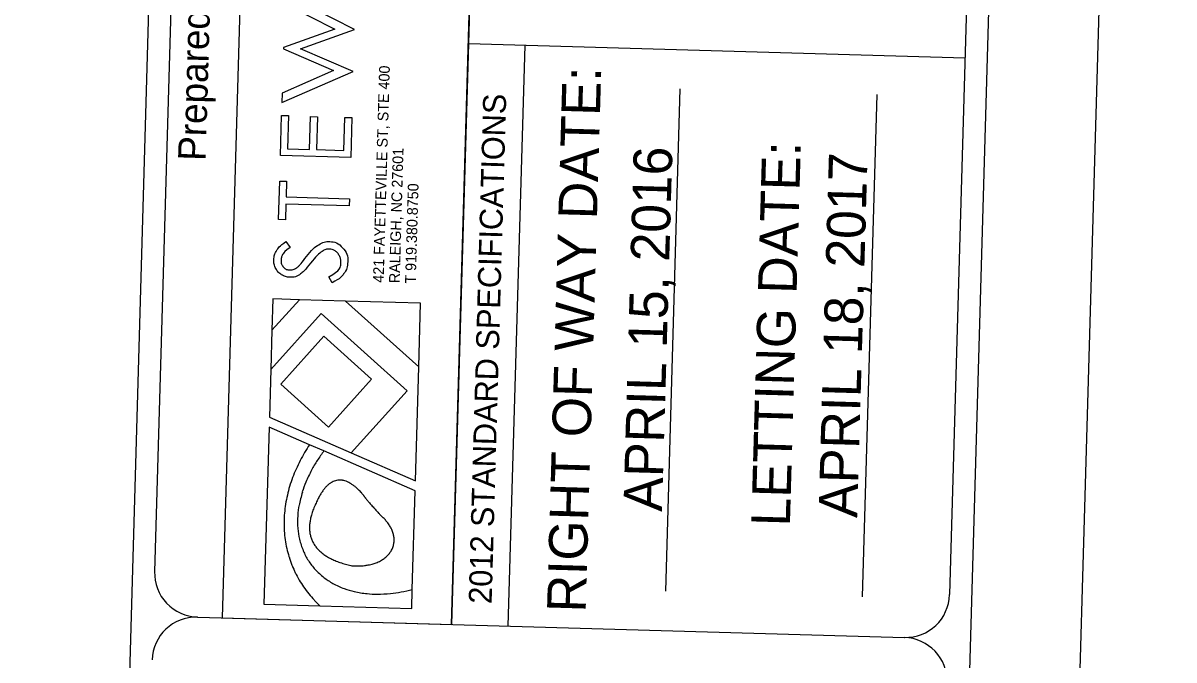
# Model space of a CAD drawing. Extents: x 2097846 to 2099709, y 989477 to 992073.
# Drawn here: x 2099177.8 to 2099568.5, y 990925.3 to 991141.6 of the extents above; entities that cross this region are included whole.
import ezdxf

# ---------------------------------------------------------------- set-up
doc = ezdxf.new("R2010")
doc.units = 0
for name, color, linetype in [('Sheet Data Field CELL', 7, 'Continuous'), ('Sheet Title CELL', 7, 'Continuous'), ('Stewart Logo', 7, 'Continuous'), ('Stewart Plot Border Xerox6279 and LJ5000', 7, 'Continuous')]:
    doc.layers.add(name, color=color, linetype=linetype)

msp = doc.modelspace()

# ---------------------------------------------------------------- linework, layer by layer
at = {"layer": 'Sheet Title CELL'}
for p, q in [((2099183.04, 989845.97), (2099244.37, 991975.08)), ((2099336.46, 991394.69), (2099328.96, 991134.63)), ((2099222.5, 990955.29), (2099234.81, 991382.61)), ((2099328.96, 991134.63), (2099323.27, 990937.38)), ((2099328.96, 991134.63), (2099497.63, 991129.77)), ((2099348.09, 991134.07), (2099342.39, 990936.83)), ((2099400.72, 991119.2), (2099395.81, 990948.65)), ((2099467.59, 991117.28), (2099462.68, 990946.72)), ((2099346.44, 991077.25), (2099346.44, 991077.25)), ((2099398.28, 991033.67), (2099398.28, 991033.67)), ((2099237.06, 990939.87), (2099476.96, 990932.96))]:
    msp.add_line(p, q, dxfattribs=at)
for points in [[(2099465.57, 989755.3), (2099529.49, 991974.37)], [(2099492.39, 990947.52), (2099504.71, 991374.84)]]:
    msp.add_lwpolyline(points, dxfattribs=at)
msp.add_lwpolyline([(2099323.27, 990937.38), (2099336.45, 991394.69), (2099258.59, 991396.94), (2099245.41, 990939.63)], close=True, dxfattribs=at)
for centre, start, end in [((2099237.42, 990954.87), 178.35, 268.35), ((2099477.32, 990947.96), 268.35, 358.35), ((2099236.56, 990924.88), 88.35, 178.35), ((2099476.46, 990917.97), 358.35, 88.35)]:
    msp.add_arc(centre, 15, start, end, dxfattribs=at)
at = {"layer": 'Stewart Logo'}
for p, q in [((2099290.24, 991139.44), (2099266.72, 991151.39)), ((2099266.63, 991148.14), (2099283.58, 991139.53)), ((2099283.58, 991139.53), (2099266.2, 991133.27)), ((2099271.99, 991132.87), (2099290.24, 991139.44)), ((2099266.2, 991133.27), (2099266.19, 991132.81)), ((2099266.19, 991132.81), (2099283.17, 991125.44)), ((2099289.83, 991125.1), (2099271.99, 991132.87)), ((2099265.66, 991114.57), (2099289.83, 991125.1)), ((2099283.17, 991125.44), (2099265.75, 991117.82)), ((2099265.75, 991117.82), (2099265.66, 991114.57)), ((2099262.54, 991047.91), (2099262.24, 991037.32)), ((2099271.56, 991047.65), (2099262.54, 991047.91)), ((2099262.24, 991037.32), (2099271.56, 991047.65)), ((2099271.56, 991047.65), (2099262.24, 991037.32)), ((2099287.27, 991047.19), (2099271.56, 991047.65)), ((2099312.7, 991046.46), (2099287.27, 991047.19)), ((2099287.27, 991047.19), (2099312.07, 991024.81)), ((2099312.07, 991024.81), (2099287.27, 991047.19)), ((2099312.07, 991024.81), (2099312.7, 991046.46)), ((2099261.85, 991023.98), (2099279.02, 991042.99)), ((2099279.02, 991042.99), (2099261.85, 991023.98)), ((2099279.02, 991042.99), (2099308.16, 991016.68)), ((2099308.16, 991016.68), (2099279.02, 991042.99)), ((2099262.24, 991037.32), (2099261.85, 991023.98)), ((2099296.11, 991020.63), (2099279.93, 991035.23)), ((2099310.96, 990986.15), (2099312.07, 991024.81)), ((2099261.85, 991023.98), (2099261.39, 991007.76)), ((2099308.16, 991016.68), (2099289.17, 990995.65)), ((2099289.17, 990995.65), (2099308.16, 991016.68)), ((2099261.39, 991007.76), (2099289.17, 990995.65)), ((2099261.29, 991004.41), (2099259.56, 990944.25)), ((2099275.05, 990998.41), (2099261.29, 991004.41)), ((2099279.92, 990996.28), (2099275.05, 990998.41)), ((2099271.84, 990993.01), (2099271.85, 990993.02)), ((2099310.86, 990982.79), (2099279.92, 990996.28)), ((2099289.17, 990995.65), (2099310.96, 990986.15)), ((2099309.9, 990949.27), (2099310.86, 990982.79)), ((2099266.88, 990978.19), (2099266.88, 990978.22)), ((2099271.52, 990977.82), (2099271.47, 990977.93)), ((2099268.03, 990960.4), (2099268.07, 990960.28)), ((2099269.05, 990957.47), (2099269.13, 990957.39)), ((2099309.71, 990942.8), (2099309.9, 990949.27)), ((2099259.56, 990944.25), (2099278.5, 990943.7)), ((2099278.5, 990943.7), (2099309.71, 990942.8))]:
    msp.add_line(p, q, dxfattribs=at)
for points in [[(2099265.14, 991096.56), (2099265.54, 991110.23), (2099267.87, 991110.16), (2099267.55, 991098.87), (2099275.02, 991098.65), (2099275.34, 991109.85), (2099277.68, 991109.78), (2099277.36, 991098.59), (2099286.72, 991098.32), (2099287.04, 991109.51), (2099289.38, 991109.45), (2099288.99, 991095.87), (2099265.14, 991096.56)], [(2099266.85, 991074.81), (2099264.52, 991074.88), (2099264.89, 991087.93), (2099267.23, 991087.86), (2099267.08, 991082.55), (2099288.59, 991081.93), (2099288.52, 991079.5), (2099267.01, 991080.12), (2099266.85, 991074.81)], [(2099267.02, 991067.38), (2099268.44, 991065.39)], [(2099282.72, 991053.38), (2099281.56, 991055.44)], [(2099281.44, 991004.38), (2099265.26, 991018.99), (2099279.93, 991035.23), (2099296.11, 991020.63), (2099281.44, 991004.38)], [(2099279.93, 991035.23), (2099265.26, 991018.99), (2099281.44, 991004.38), (2099296.11, 991020.63)], [(2099272.56, 990982.35), (2099272.62, 990982.23)], [(2099293.23, 990981.42), (2099293.33, 990981.23)], [(2099293.44, 990981.06), (2099293.6, 990980.84)], [(2099293.81, 990980.55), (2099294.08, 990980.22)], [(2099299.21, 990974.4), (2099299.48, 990974.12)], [(2099270.26, 990954.82), (2099270.15, 990955.03)], [(2099276.58, 990945.68), (2099276.69, 990945.52)]]:
    msp.add_lwpolyline(points, dxfattribs=at)
for centre, radius, start, end in [((2099319.69, 990968.23), 53.89, 145.9418, 149.2779), ((2099319.69, 990968.23), 53.89, 145.9418, 149.2779), ((2099321.71, 990967.2), 56.15, 152.6242, 155.9604), ((2099321.71, 990967.2), 56.15, 152.6242, 155.9604), ((2099319.69, 990968.23), 53.89, 149.2779, 152.6242), ((2099319.69, 990968.23), 53.89, 149.2779, 152.6242), ((2099313.79, 990969.69), 43.05, 147.1279, 152.1473), ((2099313.79, 990969.69), 43.05, 147.1279, 152.1473), ((2099317.43, 990967.34), 47.37, 142.3433, 147.1279), ((2099317.43, 990967.34), 47.37, 142.3433, 147.1279), ((2099314.06, 990970.62), 47.77, 155.9604, 159.5775), ((2099314.06, 990970.62), 47.77, 155.9604, 159.5775), ((2099323.93, 990964.33), 54.51, 152.1473, 156.9319), ((2099323.93, 990964.33), 54.51, 152.1473, 156.9319), ((2099317.02, 990969.51), 50.93, 159.5775, 163.213), ((2099317.02, 990969.51), 50.93, 159.5775, 163.213), ((2099304.36, 990972.67), 33.24, 156.9319, 163.0599), ((2099304.36, 990972.67), 33.24, 156.9319, 163.0599), ((2099286.42, 990978.96), 7.73, 122.2457, 129.1263), ((2099286.42, 990978.96), 7.73, 122.2457, 129.1263), ((2099285.58, 990980.28), 6.16, 114.5378, 122.2457), ((2099285.58, 990980.28), 6.16, 114.5378, 122.2457), ((2099285.4, 990980.69), 5.72, 106.2089, 114.5378), ((2099285.4, 990980.69), 5.72, 106.2089, 114.5378), ((2099285.27, 990981.13), 5.26, 97.5206, 106.2089), ((2099285.27, 990981.13), 5.26, 97.5206, 106.2089), ((2099285.27, 990981.12), 5.27, 88.8565, 97.5206), ((2099285.27, 990981.12), 5.27, 88.8565, 97.5206), ((2099285.26, 990980.59), 5.8, 80.5939, 88.8565), ((2099285.26, 990980.59), 5.8, 80.5939, 88.8565), ((2099285.18, 990980.12), 6.27, 72.98, 80.5939), ((2099285.18, 990980.12), 6.27, 72.98, 80.5939), ((2099284.7, 990978.55), 7.92, 66.2041, 72.98), ((2099284.7, 990978.55), 7.92, 66.2041, 72.98), ((2099284.29, 990977.63), 8.93, 60.2402, 66.2041), ((2099284.29, 990977.63), 8.93, 60.2402, 66.2041), ((2099282.75, 990974.93), 12.03, 55.1034, 60.2402), ((2099282.75, 990974.93), 12.03, 55.1034, 60.2402), ((2099312.48, 990971), 46.16, 167.0996, 171.0318), ((2099312.48, 990971), 46.16, 167.0996, 171.0318), ((2099310.92, 990971.35), 44.56, 163.213, 167.0996), ((2099310.92, 990971.35), 44.56, 163.213, 167.0996), ((2099313.79, 990969.69), 43.05, 163.0599, 169.1132), ((2099313.79, 990969.69), 43.05, 163.0599, 169.1132), ((2099299.04, 990969.46), 23.62, 148.8587, 152.2518), ((2099299.04, 990969.46), 23.62, 148.8587, 152.2518), ((2099294.38, 990972.28), 18.17, 144.971, 148.8587), ((2099294.38, 990972.28), 18.17, 144.971, 148.8587), ((2099290.38, 990975.08), 13.29, 140.4253, 144.971), ((2099290.38, 990975.08), 13.29, 140.4253, 144.971), ((2099289.16, 990976.09), 11.7, 135.194, 140.4253), ((2099289.16, 990976.09), 11.7, 135.194, 140.4253), ((2099287.03, 990978.21), 8.7, 129.1263, 135.194), ((2099287.03, 990978.21), 8.7, 129.1263, 135.194), ((2099281.81, 990973.59), 13.67, 50.6411, 55.1034), ((2099281.81, 990973.59), 13.67, 50.6411, 55.1034), ((2099278.64, 990969.72), 18.67, 46.824, 50.6411), ((2099278.64, 990969.72), 18.67, 46.824, 50.6411), ((2099274.82, 990965.65), 24.25, 43.4909, 46.824), ((2099274.82, 990965.65), 24.25, 43.4909, 46.824), ((2099279, 990969.62), 18.49, 39.6738, 43.4909), ((2099279, 990969.62), 18.49, 39.6738, 43.4909), ((2099296.28, 990982.77), 3.33, 203.8541, 206.4104), ((2099293.91, 990981.59), 0.68, 206.4103, 212.0676), ((2099308.49, 990971.65), 42.12, 171.0318, 175.1641), ((2099308.49, 990971.65), 42.12, 171.0318, 175.1641), ((2099298.8, 990972.68), 27.83, 169.1132, 176.6486), ((2099298.8, 990972.68), 27.83, 169.1132, 176.6486), ((2099303.1, 990966.26), 28.67, 156.1495, 159.8788), ((2099303.1, 990966.26), 28.67, 156.1495, 159.8788), ((2099297.87, 990968.57), 22.95, 151.9816, 156.1495), ((2099297.87, 990968.57), 22.95, 151.9816, 156.1495), ((2099294.06, 990972.08), 17.99, 152.2518, 156.1394), ((2099294.06, 990972.08), 17.99, 152.2518, 156.1394), ((2099297.13, 990983.61), 4.48, 212.0675, 214.6237), ((2099297.13, 990983.61), 4.48, 212.0675, 214.6237), ((2099300.49, 990985.93), 8.57, 214.6237, 216.4714), ((2099308.09, 990991.55), 18.02, 216.4714, 217.5989), ((2099308.09, 990991.55), 18.02, 216.4714, 217.5989), ((2099314.39, 990996.4), 25.97, 217.5989, 218.5383), ((2099327.78, 991007.06), 43.09, 218.5383, 219.2146), ((2099327.78, 991007.06), 43.09, 218.5383, 219.2146), ((2099337.08, 991014.65), 55.09, 219.2146, 219.8128), ((2099337.08, 991014.65), 55.09, 219.2146, 219.8128), ((2099351.65, 991026.8), 74.06, 219.8128, 220.3011), ((2099351.65, 991026.8), 74.06, 219.8128, 220.3011), ((2099363.88, 991037.17), 90.1, 220.3011, 220.7439), ((2099363.88, 991037.17), 90.1, 220.3011, 220.7439), ((2099370.57, 991042.93), 98.93, 220.7439, 221.1471), ((2099370.57, 991042.93), 98.93, 220.7439, 221.1471), ((2099385.16, 991055.68), 118.3, 221.1471, 221.5158), ((2099385.16, 991055.68), 118.3, 221.1471, 221.5158), ((2099308.49, 990971.65), 42.12, 175.1641, 179.3637), ((2099308.49, 990971.65), 42.12, 175.1641, 179.3637), ((2099303.56, 990972.4), 32.6, 176.6486, 184.3198), ((2099303.56, 990972.4), 32.6, 176.6486, 184.3198), ((2099292.93, 990969.59), 17.96, 164.0466, 168.7766), ((2099292.93, 990969.59), 17.96, 164.0466, 168.7766), ((2099297.89, 990968.17), 23.13, 159.8788, 164.0466), ((2099297.89, 990968.17), 23.13, 159.8788, 164.0466), ((2099376.9, 991048.37), 107.27, 221.5158, 221.8864), ((2099376.9, 991048.37), 107.27, 221.5158, 221.8864), ((2099392.11, 991062.01), 127.7, 221.8863, 222.2259), ((2099392.11, 991062.01), 127.7, 221.8863, 222.2259), ((2099369.73, 991041.7), 97.48, 222.2259, 222.5983), ((2099369.73, 991041.7), 97.48, 222.2259, 222.5983), ((2099382.96, 991053.87), 115.46, 222.5983, 222.9405), ((2099382.96, 991053.87), 115.46, 222.5983, 222.9405), ((2099354.18, 991027.08), 76.14, 222.9405, 223.345), ((2099354.18, 991027.08), 76.14, 222.9405, 223.345), ((2099363.5, 991035.88), 88.95, 223.345, 223.7193), ((2099363.5, 991035.88), 88.95, 223.345, 223.7193), ((2099333.62, 991007.31), 47.61, 223.7193, 224.1914), ((2099353.79, 991026.91), 75.73, 224.1914, 224.5657), ((2099353.79, 991026.91), 75.73, 224.1914, 224.5657), ((2099290.9, 990963.84), 13.35, 42.4064, 48.0117), ((2099290.9, 990963.84), 13.35, 42.4064, 48.0117), ((2099306.08, 990971.68), 39.71, 179.3637, 183.6885), ((2099306.08, 990971.68), 39.71, 179.3637, 183.6885), ((2099294.58, 990971.72), 23.59, 184.3198, 193.3394), ((2099294.58, 990971.72), 23.59, 184.3198, 193.3394), ((2099288.2, 990970.23), 13.19, 174.0321, 179.8893), ((2099288.2, 990970.23), 13.19, 174.0321, 179.8893), ((2099287.26, 990970.23), 12.25, 179.8893, 186.2513), ((2099287.26, 990970.23), 12.25, 179.8893, 186.2513), ((2099291.38, 990969.9), 16.38, 168.7766, 174.0321), ((2099291.38, 990969.9), 16.38, 168.7766, 174.0321), ((2099291.33, 990964.23), 12.77, 36.6753, 42.4064), ((2099291.33, 990964.23), 12.77, 36.6753, 42.4064), ((2099289.29, 990962.72), 15.31, 31.0699, 36.6753), ((2099289.29, 990962.72), 15.31, 31.0699, 36.6753), ((2099294.75, 990966.01), 8.93, 23.7286, 31.0699), ((2099294.75, 990966.01), 8.93, 23.7286, 31.0699), ((2099292.51, 990965.02), 11.39, 16.3599, 23.7286), ((2099292.51, 990965.02), 11.39, 16.3599, 23.7286), ((2099305.36, 990971.63), 38.99, 183.6885, 188.0934), ((2099305.36, 990971.63), 38.99, 183.6885, 188.0934), ((2099304.85, 990971.56), 38.47, 188.0934, 192.5276), ((2099304.85, 990971.56), 38.47, 188.0934, 192.5276), ((2099296.1, 990972.08), 25.15, 193.3394, 202.6071), ((2099296.1, 990972.08), 25.15, 193.3394, 202.6071), ((2099285.66, 990970.06), 10.64, 186.2513, 193.0781), ((2099285.66, 990970.06), 10.64, 186.2513, 193.0781), ((2099285.3, 990969.97), 10.27, 193.0781, 200.1773), ((2099285.3, 990969.97), 10.27, 193.0781, 200.1773), ((2099285.04, 990969.88), 9.99, 200.1773, 207.3755), ((2099285.04, 990969.88), 9.99, 200.1773, 207.3755), ((2099296.44, 990966.18), 7.28, 7.1425, 16.3599), ((2099296.44, 990966.18), 7.28, 7.1425, 16.3599), ((2099297.11, 990965.94), 6.63, 347.2683, 357.8588), ((2099297.11, 990965.94), 6.63, 347.2683, 357.8588), ((2099295.12, 990966.01), 8.62, 357.8588, 7.1425), ((2099295.12, 990966.01), 8.62, 357.8588, 7.1425), ((2099303.29, 990971.21), 36.88, 192.5276, 197.0444), ((2099303.29, 990971.21), 36.88, 192.5276, 197.0444), ((2099293.17, 990970.86), 21.99, 202.6071, 212.5217), ((2099293.17, 990970.86), 21.99, 202.6071, 212.5217), ((2099285.2, 990969.96), 10.17, 207.3755, 214.4498), ((2099285.2, 990969.96), 10.17, 207.3755, 214.4498), ((2099286.02, 990970.53), 11.17, 214.4498, 221.1992), ((2099286.02, 990970.53), 11.17, 214.4498, 221.1992), ((2099286.58, 990971.01), 11.91, 221.1992, 227.5039), ((2099286.58, 990971.01), 11.91, 221.1992, 227.5039), ((2099288.24, 990972.82), 14.37, 227.5039, 233.2446), ((2099288.24, 990972.82), 14.37, 227.5039, 233.2446), ((2099295.96, 990966.36), 7.86, 316.7584, 326.5336), ((2099295.96, 990966.36), 7.86, 316.7584, 326.5336), ((2099296.36, 990966.1), 7.39, 326.5336, 336.918), ((2099296.36, 990966.1), 7.39, 326.5336, 336.918), ((2099296.32, 990966.11), 7.44, 336.918, 347.2683), ((2099296.32, 990966.11), 7.44, 336.918, 347.2683), ((2099304.85, 990971.56), 38.47, 197.0444, 201.4827), ((2099304.85, 990971.56), 38.47, 197.0444, 201.4827), ((2099292.99, 990970.75), 21.77, 212.5217, 222.5317), ((2099292.99, 990970.75), 21.77, 212.5217, 222.5317), ((2099289.06, 990973.92), 15.74, 233.2446, 238.4409), ((2099289.06, 990973.92), 15.74, 233.2446, 238.4409), ((2099291.28, 990977.54), 19.99, 238.4409, 243.0517), ((2099291.28, 990977.54), 19.99, 238.4409, 243.0517), ((2099292.22, 990979.38), 22.05, 243.0517, 247.1753), ((2099292.22, 990979.38), 22.05, 243.0517, 247.1753), ((2099294.74, 990985.36), 28.54, 247.1753, 250.7997), ((2099294.74, 990985.36), 28.54, 247.1753, 250.7997), ((2099296.97, 990991.77), 35.32, 250.7997, 254.0433), ((2099296.97, 990991.77), 35.32, 250.7997, 254.0433), ((2099291.24, 990976.26), 19.06, 281.3051, 286.5336), ((2099291.24, 990976.26), 19.06, 281.3051, 286.5336), ((2099293.2, 990969.62), 12.14, 286.5336, 293.0857), ((2099293.2, 990969.62), 12.14, 286.5336, 293.0857), ((2099292.47, 990971.34), 14.01, 293.0857, 299.8598), ((2099292.47, 990971.34), 14.01, 293.0857, 299.8598), ((2099294.66, 990967.54), 9.62, 299.8598, 308.0357), ((2099294.66, 990967.54), 9.62, 299.8598, 308.0357), ((2099294.5, 990967.73), 9.87, 308.0357, 316.7584), ((2099294.5, 990967.73), 9.87, 308.0357, 316.7584), ((2099302.38, 990970.48), 35.74, 201.4827, 205.9986), ((2099302.38, 990970.48), 35.74, 201.4827, 205.9986), ((2099305.13, 990972.09), 38.92, 205.9986, 210.3305), ((2099305.13, 990972.09), 38.92, 205.9986, 210.3305), ((2099294.67, 990972.29), 24.05, 222.5317, 232.0541), ((2099294.67, 990972.29), 24.05, 222.5317, 232.0541), ((2099295.03, 990985.01), 28.29, 254.0433, 257.6676), ((2099295.03, 990985.01), 28.29, 254.0433, 257.6676), ((2099291.4, 990977.92), 20.69, 263.3079, 267.462), ((2099291.4, 990977.92), 20.69, 263.3079, 267.462), ((2099291.31, 990975.72), 18.49, 267.462, 271.8567), ((2099291.31, 990975.72), 18.49, 267.462, 271.8567), ((2099291.13, 990981.09), 23.86, 271.8567, 276.0109), ((2099291.13, 990981.09), 23.86, 271.8567, 276.0109), ((2099292.09, 990971.97), 14.69, 276.0109, 281.305), ((2099292.09, 990971.97), 14.69, 276.0109, 281.305), ((2099302.38, 990970.48), 35.74, 210.3305, 214.7327), ((2099302.38, 990970.48), 35.74, 210.3305, 214.7327), ((2099306.39, 990973.26), 40.61, 214.7327, 218.862), ((2099306.39, 990973.26), 40.61, 214.7327, 218.862), ((2099293.56, 990970.86), 22.24, 232.0541, 241.452), ((2099293.56, 990970.86), 22.24, 232.0541, 241.452), ((2099297.35, 990977.82), 30.17, 241.452, 249.5184), ((2099297.35, 990977.82), 30.17, 241.452, 249.5184), ((2099304.23, 990971.52), 37.84, 218.862, 223.0565), ((2099304.23, 990971.52), 37.84, 218.862, 223.0565), ((2099295.76, 990973.58), 25.64, 249.5184, 257.4775), ((2099295.76, 990973.58), 25.64, 249.5184, 257.4775), ((2099298.8, 990987.27), 39.66, 257.4775, 263.8751), ((2099298.8, 990987.27), 39.66, 257.4775, 263.8751), ((2099297.84, 990978.33), 30.66, 263.8751, 270.3368), ((2099297.84, 990978.33), 30.66, 263.8751, 270.3368), ((2099297.73, 990998.36), 50.7, 270.3368, 275.3612), ((2099297.73, 990998.36), 50.7, 270.3368, 275.3612), ((2099298.68, 990988.21), 40.5, 275.3612, 280.604), ((2099298.68, 990988.21), 40.5, 275.3612, 280.604), ((2099298.02, 990991.74), 44.1, 280.604, 285.6284), ((2099298.02, 990991.74), 44.1, 280.604, 285.6284), ((2099305.13, 990972.09), 38.92, 223.0565, 226.8346), ((2099305.13, 990972.09), 38.92, 223.0565, 226.8346)]:
    msp.add_arc(centre, radius, start, end, dxfattribs=at)
for points in [[(2099281.56, 991055.44), (2099285.56, 991057.46), (2099285.64, 991060.26), (2099285.68, 991061.46), (2099285.15, 991062.53), (2099284.62, 991063.6), (2099283.7, 991064.18), (2099282.77, 991064.76), (2099281.72, 991064.79), (2099280.52, 991064.82), (2099279.35, 991064.05), (2099277.73, 991062.97), (2099275.4, 991060.07), (2099273.07, 991057.16), (2099272.04, 991056.46), (2099270.32, 991055.24), (2099268.35, 991055.3), (2099266.8, 991055.34), (2099265.54, 991056.12), (2099264.28, 991056.91), (2099263.58, 991058.28), (2099262.88, 991059.65), (2099262.93, 991061.24), (2099262.97, 991062.92), (2099263.85, 991064.36), (2099264.73, 991065.81), (2099267.02, 991067.38)], [(2099268.44, 991065.39), (2099266.62, 991064.09), (2099266.02, 991063.16), (2099265.43, 991062.23), (2099265.4, 991061.11), (2099265.35, 991059.67), (2099266.2, 991058.73), (2099267.05, 991057.79), (2099268.33, 991057.75), (2099269.11, 991057.73), (2099269.85, 991058.03), (2099270.59, 991058.34), (2099271.47, 991059.17), (2099271.94, 991059.63), (2099273.94, 991062.18), (2099276.31, 991065.21), (2099278.13, 991066.31), (2099279.95, 991067.41), (2099281.74, 991067.36), (2099284.34, 991067.28), (2099286.19, 991065.26), (2099288.05, 991063.24), (2099287.97, 991060.42), (2099287.9, 991058.25), (2099286.69, 991056.52), (2099285.48, 991054.79), (2099282.72, 991053.38)]]:
    msp.add_open_spline(points, degree=3, dxfattribs=at)
at = {"layer": 'Stewart Plot Border Xerox6279 and LJ5000'}
msp.add_lwpolyline([(2099495.04, 989476.82), (2099568.48, 992025.76), (2097919.17, 992073.28), (2097845.72, 989524.34)], close=True, dxfattribs=at)

# ---------------------------------------------------------------- texts
at = {"layer": 'Sheet Data Field CELL'}
for s, p in [('APRIL 15, 2016', (2099394.67, 990975.59)), ('APRIL 18, 2017', (2099460.92, 990973.49))]:
    msp.add_text(s, height=13.1252, rotation=88.35, dxfattribs=at).set_placement(p)
at = {"layer": 'Sheet Title CELL'}
for s, height, p in [('Prepared in the Offices of:', 9.375, (2099239.74, 991094.68)), ('RIGHT OF WAY DATE: ', 13.1247, (2099368.74, 990941.33)), ('2012 STANDARD SPECIFICATIONS', 7.8, (2099336.83, 990944.26)), ('LETTING DATE:', 13.1247, (2099438.08, 990970.56))]:
    msp.add_text(s, height=height, rotation=88.35, dxfattribs=at).set_placement(p)
at = {"layer": 'Stewart Logo'}
for s, p in [('421 FAYETTEVILLE ST, STE 400', (2099300.17, 991053.36)), ('RALEIGH, NC 27601', (2099305.62, 991053.21)), ('T 919.380.8750', (2099311.07, 991053.05))]:
    msp.add_text(s, height=3.6351, rotation=88.3496, dxfattribs=at).set_placement(p)

doc.saveas('drawing.dxf')
